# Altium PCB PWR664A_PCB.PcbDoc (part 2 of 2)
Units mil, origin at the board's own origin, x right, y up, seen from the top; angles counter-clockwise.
Board outline 3000 x 3000 mil, 4 copper layers (Top Layer, MidLayer1, MidLayer2, Bottom Layer), stack 31 mil thick; 122 components, 46 nets, 275 pads, 124 vias.
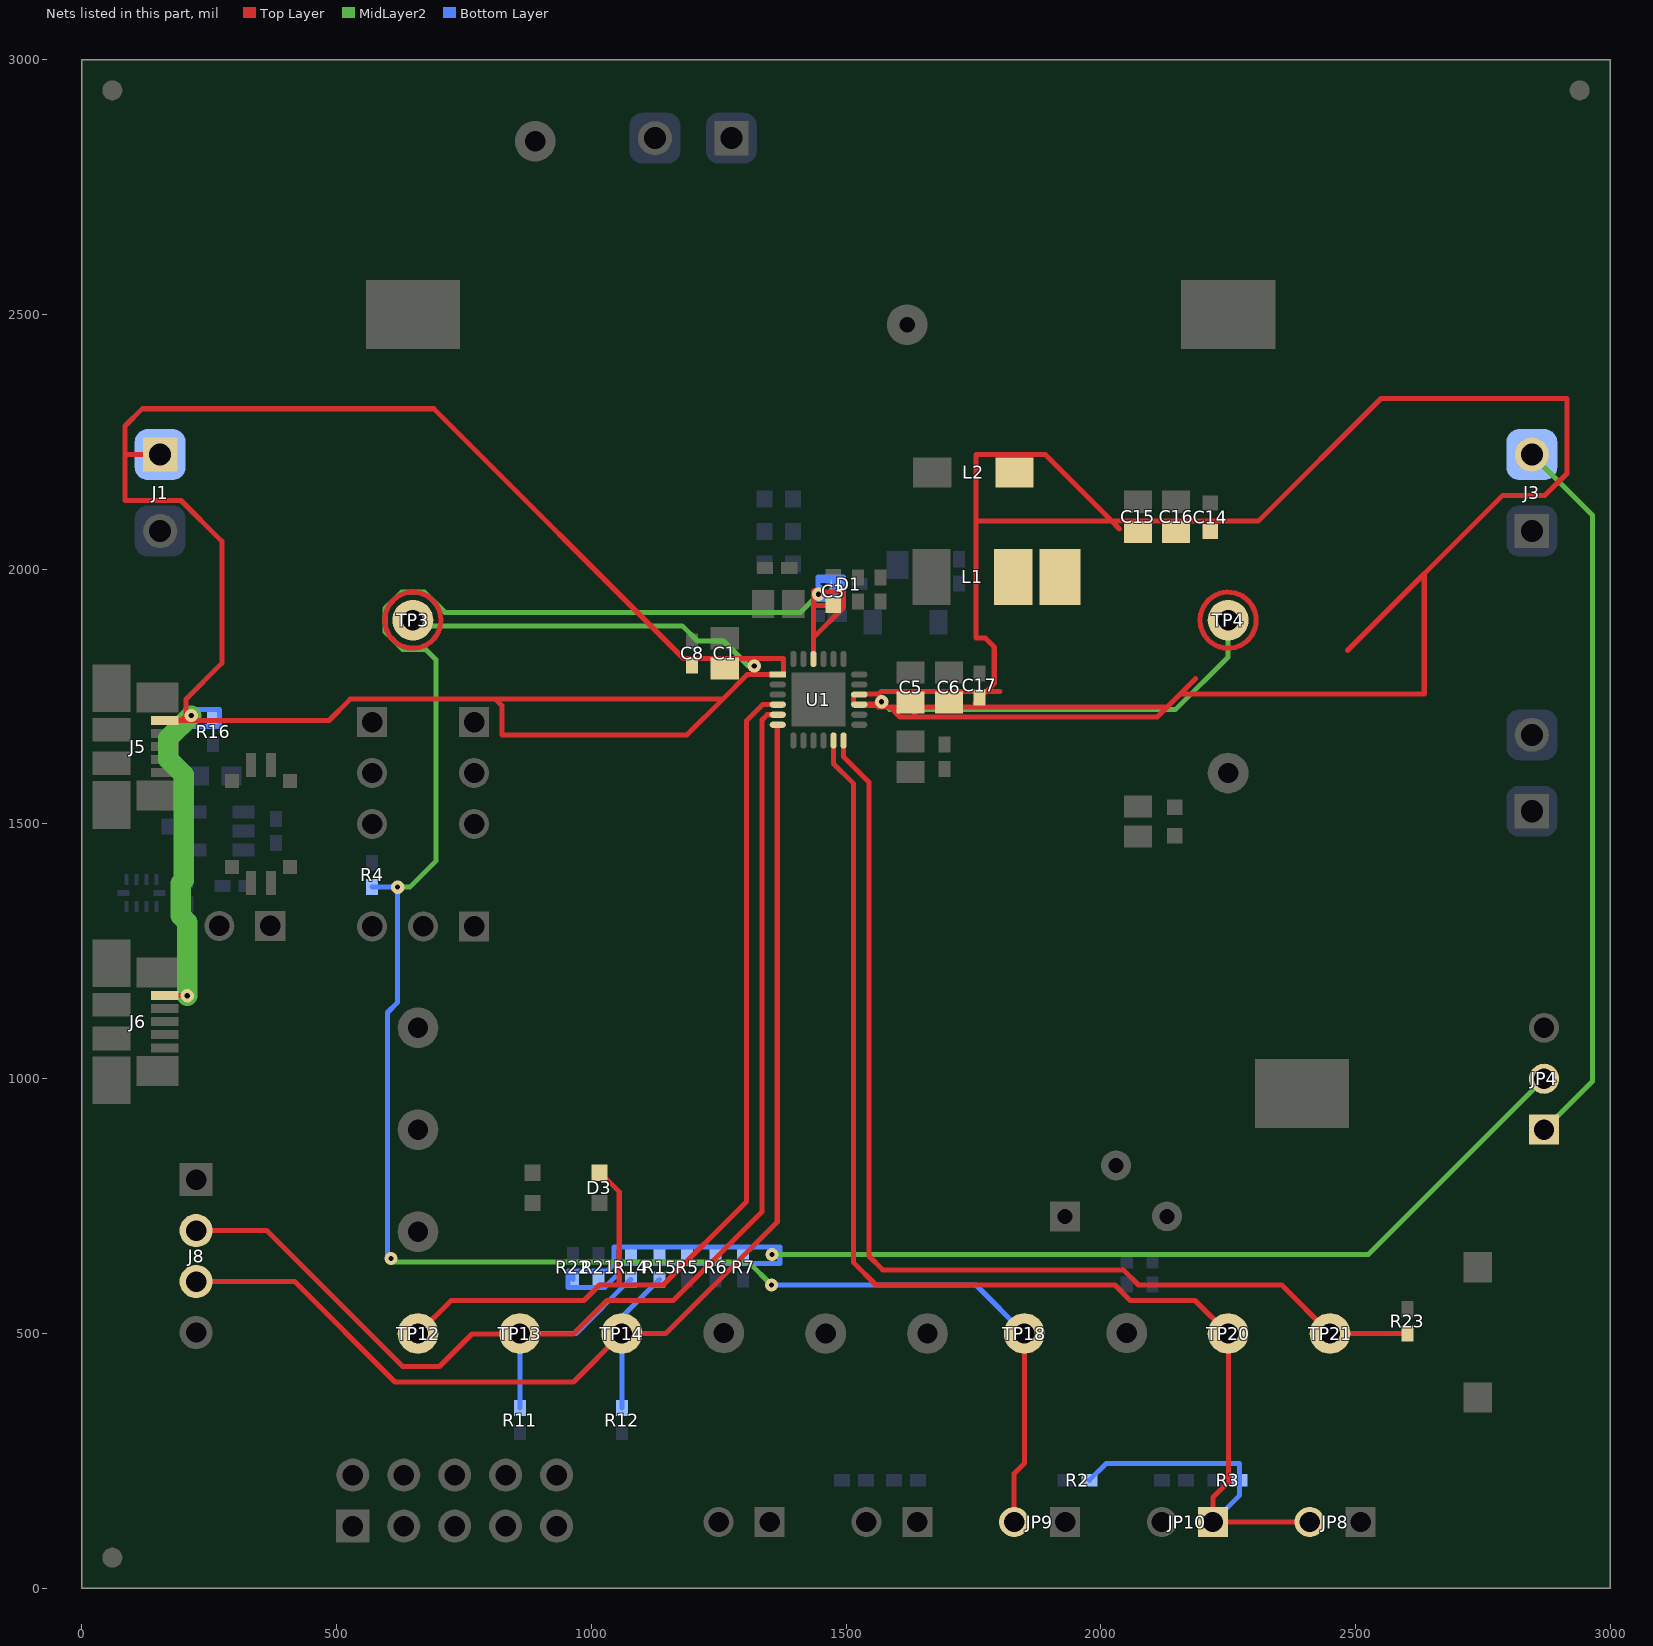
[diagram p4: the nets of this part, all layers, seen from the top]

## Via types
v1: diameter 26, hole 10, Top Layer to Bottom Layer, tented both sides, 115 vias
v2: diameter 26, hole 10, Top Layer to Bottom Layer, tented bottom, 9 vias

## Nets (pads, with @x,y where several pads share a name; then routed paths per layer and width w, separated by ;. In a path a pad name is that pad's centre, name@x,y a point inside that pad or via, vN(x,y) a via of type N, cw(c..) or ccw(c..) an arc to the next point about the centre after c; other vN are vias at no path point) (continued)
PULL-UP: JP4.2 R5.1 R6.1 R7.1 R14.1 R15.1 R21.2 R22.2 | length 2643
  MidLayer2 w10: v1(1355,655) 2525,655 JP4.2@2870,1000
  Bottom Layer w10: R22.2@964,606.38 964,612.87 954,622.87 ; 954,622.87 954,590 1026,590 1051.19,615.19 1051.19,628.34 1059.98,637.13 1370,637.13 1370,670 1045,670 1045,635.85 1032.02,622.87 954,622.87
QON: R23.2 TP21.1 U1.12 | length 2152.7
  Top Layer w10: U1.12@1495.21,1664 1495.21,1631.79 1545,1582 1545,652 1572,625 2044,625 2074,595 2355,595 TP21.1@2450,500 2601.62,500 R23.2@2602,500.38
REGN: C3.2 D1.2 JP9.2 R4.2 TP18.1 U1.22 | length 4684.4
  Top Layer w10: U1.22@1436.16,1824 1436.16,1956.87 v1@1437.47,1958.19 ; 1436.47,1866.47 1495,1925 1495,1955 1453.79,1955 1450.6,1958.19 v1@1437.47,1958.19 ; C3.2@1475,1929 1437.47,1929 v1@1437.47,1958.19 ; JP9.2@1830,130 1830,225 1850,245 TP18.1@1850,500
  MidLayer2 w10: v1(607,647) 614,640 1309,640 v1(1354,595) ; v1(620,1376) 644,1376 695,1427 695,1822.78 674.78,1843 629.22,1843 595,1877.22 595,1922.78 627.22,1955 672.78,1955 712.78,1915 1410,1915 v1(1446,1951)
  Bottom Layer w10: R4.2@570,1376.38 570.38,1376 v1(620,1376) 620,1150 600,1130 600,654 v1(607,647) ; v1@1346,595 v1(1354,595) 1755,595 TP18.1@1850,500 ; v1@1445,1952 v1@1445,1958 ; 1451,1964 v1@1445,1958 ; 1466.09,1978 1446,1978 1445,1977 ; 1478,1941 1478,1985 ; v1@1445,1958 1445,1977 ; v1@1445,1958 1438,1951 1438,1946 1443,1941 1495,1941 1495,1985 1478,1985 ; 1445,1977 1445,1985 1478,1985
SCL: J8.2 R11.1 R14.2 TP13.1 U1.5 | length 2755.9
  Top Layer w10: J8.2@224.41,702 363,702 630,435 702,435 766,499 965,499 1031,565 1161,565 1335,739 1335,1704 1345.47,1714.47 U1.5@1366,1714.47
  Bottom Layer w10: R11.1@860,353.62 TP13.1@860,500 970,500 1076.38,606.38 R14.2@1078,606.38
SDA: J8.3 R12.2 R15.2 TP14.1 U1.6 | length 2606.4
  Top Layer w10: J8.3@224.41,602 418,602 615,405 965,405 TP14.1@1060,500 1146,500 1365,719 U1.6@1365,1689.79
  Bottom Layer w10: R12.2@1060,353.62 TP14.1@1060,500 1060,532.38 R15.2@1134,606.38
STAT: D3.2 TP12.1 U1.4 | length 2006.7
  Top Layer w10: TP12.1@660,500 725,565 986,565 1016,595 1141,595 1305,759 1305,1703 1336.16,1734.16 U1.4@1366,1734.16 ; D3.2@1016,815.53 1017.47,815.53 1055,778 1055,596
SYS: C5.1 C6.1 C14.1 C15.1 C16.1 C17.1 J3.2 JP4.1 L1.2 L2.2 pad.0@1920,1985 pad.4 TP4.1 U1.15 U1.16 | length 7754.8
  Top Layer w10: U1.15@1515,1735.47 U1.16@1515,1753.84 ; U1.16@1526,1753.84 1527.16,1755 1564,1755 ; 1565,1756 1569,1760 1775.28,1760 ; C5.1@1627,1738.47 1634,1731.47 C5.1@1634,1730 ; C17.1@1753.28,1738 1775.28,1760 ; 1802,1760 1775.28,1760 ; 2037,2079 2021,2095 ; 2131,1730 C5.1@1634,1730 ; 2156,1755 2635,1755 2635,1991 ; 2186,1785 2111,1710 1634,1710 ; 2484.5,1840.5 2789,2145 2872,2145 2915,2188 2915,2334 2914,2335 2550,2335 2310,2095 2021,2095 ; v1@1559.13,1733.16 1562.73,1730.42 1563.28,1730 v1@1577,1730 ; v1@1559.13,1733.16 1526,1733.16 1526,1735.47 1557.81,1735.47 v1@1559.13,1733.16 ; v1@1559.13,1733.16 1570.44,1733.98 1572.84,1734.16 v1@1577,1730 ; v1@1577,1730 1586,1730 ; 1586,1730 1606,1710 1634,1710 ; 1586,1730 C5.1@1634,1730 ; 1634,1710 C5.1@1634,1730 ; 1755,2095 1755,1865 1773.28,1865 1791,1847.28 1791,1775.72 1775.28,1760 ; 1755,2095 1755,2225 1891,2225 2021,2095 ; 1755,2095 2021,2095 ; 2305,1900 ccw(c2250,1900) 2305,1900
  MidLayer2 w10: v1(1570,1740) 1585,1725 2147,1725 2250,1828 TP4.1@2250,1900 ; J3.2@2846,2225 2965,2106 2965,995 JP4.1@2870,900
TS: JP8.2 JP10.1 R2.1 R3.2 TP20.1 U1.11 | length 2849.8
  Top Layer w10: U1.11@1475.53,1664 1475.53,1618.47 1515,1579 1515,639 1559,595 2028,595 2058,565 2185,565 TP20.1@2250,500 ; TP20.1@2251,500 2251,209 2220,178 JP10.1@2220,130 JP8.2@2410,130
  Bottom Layer w10: R2.1@1977.62,212 2010.62,245 2272,245 2272,216.62 R3.2@2270,214.62 ; JP10.1@2220,130 2272.62,182.62 R3.2@2272.62,212
VBUS: C1.1 C8.1 J1.1 J5.1 J6.1 pad.1 R16.1 TP3.1 U1.1 | length 6071.1
  Top Layer w10: J1.1@154,2225 85,2225 ; J6.1@162.61,1163.18 206.82,1163.18 v1(207,1163) ; U1.1@1366,1793.21 1306.21,1793.21 1258,1745 ; U1.1@1377,1793 1377,1825 1181,1825 691,2315 119,2315 85,2281 85,2225 ; 85,2225 85,2135 195,2135 275,2055 275,1815.57 204.98,1745.54 204.98,1712.72 196.19,1703.93 163.36,1703.93 J5.1@162.61,1703.18 485.18,1703.18 527,1745 812,1745 ; 812,1745 1258,1745 ; 812,1745 825,1732 825,1675 1188,1675 1258,1745 ; 705,1900 ccw(c650,1900) 705,1900
  MidLayer2 w10: TP3.1@650,1900 661,1889 1178.4,1889 1208.4,1859 1259.69,1859 1308.69,1810 v1(1320,1810)
  MidLayer2 w40: v1(207,1163) 207,1307 194,1320 194,1383.81 200,1389.81 200,1597 170,1627 170,1668 v1(215,1713)
  Bottom Layer w10: v1(215,1713) v1@215,1725 ; v1@215,1725 270,1725 270,1691 205,1691 205,1725 v1@215,1725
pads on no net: FID1.1 FID2.1 FID3.1 H1.0 H2.0 H3.0 H4.0 J7.1 J7.3 J7.4 J7.5 J7.7 J7.8 SH-JP1.0 SH-JP2.0 SH-JP3.0 SH-JP4.0 SH-JP5.0 SH-JP9.0 SH-JP10.0

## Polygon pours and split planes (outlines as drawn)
AGND on Top Layer "Top Layer-No Net" (solid, remove dead copper, pour order 2): 2980,1280 2980,30 1540,30 1541,31 1541,131 1541,132 1659,250 1656,253 1656,502 1562,502 1560,500 1545,515 1545,516 1545,1280 2980,1280
PGND on Top Layer "Top Layer-No Net 1" (solid, remove dead copper, pour order 4): 1540,30 1540,129 1542,131 1661,250 1661,1710 1660,1711 207,1711 205.17,1709.17 205.17,1518.17 204.17,1518.17 129,1443 125,1439 125,1331 125,1294 185,1234 200,1234 200,1130 200,1045 185,1027 178,1020 20,1020 20,120 90,120 120,90 120,30
AGND on MidLayer2 "MidLayer2-No Net" (solid, remove dead copper, pour order 6): 20,2980 2980,2980 2980,20 20,20 20,2980
PGND on MidLayer1 "MidLayer1-No Net" (solid, remove dead copper, pour order 8): 20,2980 2980,2980 2980,20 20,20 20,2980
PGND on Bottom Layer "Bottom Layer-No Net" (solid, remove dead copper, pour order 12): 20,2980 2980,2980 2980,20 20,20 20,2980

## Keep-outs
Keep-Out Layer:
  lines w5: -5,0 ccw(c0,0) 0,-5 3000,-5 ccw(c3000,0) 3005,0 3005,3000 ccw(c3000,3000) 3000,3005 0,3005 ccw(c0,3000) -5,3000 -5,0
  text "Keep-Out Layer" at 577,-858.49 h60

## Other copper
Top Layer:
  rectangle net PGND: 1666,2436 1681,2456
  rectangle net VBUS: 647,2116 765,2204
  rectangle net VBUS: 928,1770 1068,1942
  rectangle net VBUS: 820,1734 831,1743
  rectangle net PGND: 59,2290 67,2296
  rectangle net VBUS: 85,2136 124,2284
  rectangle net VBUS: 117,2134 692,2317
  region net VBUS: 1119,1755 1184,1820 689,2315 624,2250
  rectangle net PGND: 181,980 209,1045
  rectangle net PGND: 83,1307 112,1451
  rectangle net PGND: 91,1197 115,1252
  rectangle net PGND: 81,1529 115,1585
  region net PGND: 84,1420 190,1526 138,1578 32,1472
  region net PGND: 147,1195 190,1238 89,1339 46,1296
  rectangle net PGND: 88,1179 108,1203
  rectangle net PGND: 80,987 111,1045
  rectangle net PGND: 20,850 96,1726
  region net BAT: 2731.5,1533.5 2793,1595 2734.5,1653.5 2673,1592
  region net PGND: 2755,1446 2842.5,1533.5 2803,1573 2715.5,1485.5
  region net PGND: 2922,1553 2943,1574 2928,1589 2907,1568
  region net PGND: 2890,2842 2915.5,2867.5 2874,2909 2848.5,2883.5
  region net PGND: 2935.14,2342.14 2950,2357 2937.14,2369.86 2922.28,2355
  region net SYS: 2869.5,2144.5 2914,2189 2870.5,2232.5 2826,2188
  region net PGND: 2904,2085 2966,2147 2935,2178 2873,2116
  region net PGND: 2707,1935 2848,2076 2799,2125 2658,1984
  region net SYS: 2630.5,1987.5 2787,2144 2688.5,2242.5 2532,2086
  region net SYS: 2356,2008 2616.5,2268.5 2552,2333 2291.5,2072.5
  rectangle net PMID: 847,2797 905,2871
  region net PGND: 1552,1773 1608,1829 1592,1845 1536,1789
  region net NetC4_1: 1598,1907 1632.5,1941.5 1604,1970 1569.5,1935.5
  region net NetC4_1: 1490,1835 1505.5,1850.5 1494,1862 1478.5,1846.5
  region net NetC4_1: 1533,1820 1587.86,1874.86 1555,1907.72 1500.14,1852.86
  region net PMID: 1384,2614 1444.5,2674.5 1344,2775 1283.5,2714.5
  region net PGND: 1467.64,2679.64 1543,2755 1427.64,2870.36 1352.28,2795
  region net PGND: 1226.5,2883.5 1248,2905 1208.5,2944.5 1187,2923
  region net PMID: 1174,2840.5 1206.75,2873.25 1176,2904 1143.25,2871.25
  region net PMID: 1216,2737 1241.5,2762.5 1207,2797 1181.5,2771.5
  region net PMID: 1269,2462 1383,2576 1072,2887 958,2773
  region net PMID: 881,2836 913,2868 876,2905 844,2873
  region net PGND: 816.5,2876.5 865,2925 832.5,2957.5 784,2909
  region net PMID: 874,2774 906,2806 877,2835 845,2803
  region net PGND: 849,2724 872.36,2747.36 825,2794.72 801.64,2771.36
  region net PGND: 192.5,1763.5 252,1823 215.5,1859.5 156,1800
  region net VBUS: 243,1709 312.5,1778.5 276,1815 206.5,1745.5
  region net VBUS: 490.5,1706.5 526,1742 494.5,1773.5 459,1738
  region net VBUS: 1186.5,1674.5 1304,1792 1269.5,1826.5 1152,1709
  region net PMID: 1380,2021 1426,2067 1324,2169 1278,2123
  region net PGND: 1312,1998 1343,2029 1256,2116 1225,2085
  region net PGND: 204,1999 254.5,2049.5 189,2115 138.5,2064.5
  region net VBUS: 291,2041 351,2101 257,2195 197,2135
  region net PGND: 66,2101 80,2115 65,2130 51,2116
  region net VBUS: 103,2259 136.5,2292.5 116,2313 82.5,2279.5
  region net PGND: 64,2292 107,2335 79,2363 36,2320
  region net PGND: 102,2842 145,2885 125,2905 82,2862
  rectangle net PGND: 50,2020 189,2115
  rectangle net VBUS: 1224,1748 1266,1800
  rectangle net VBUS: 1182,1718 1227,1806
  rectangle net VBUS: 1176,1793 1211,1800
  rectangle net VBUS: 1188,1793 1377,1825
  rectangle net VBUS: 825,1678 1192,1826
  rectangle net VBUS: 206,1704 487,1749
  rectangle net PGND: 185,1794 220,1825
  rectangle net PGND: 58,1771 193,1829
  rectangle net PGND: 49,1831 112,1834
  rectangle net PGND: 93,1719 112,1830
  rectangle net PGND: 36,1822 254.64,2047.08
  rectangle net PGND: 25,1822 62,2349
  rectangle net PGND: 1048,1997 1296,2080
  rectangle net PGND: 1106,1941 1332,2041
  rectangle net PGND: 976,2074 1256,2245
  rectangle net PMID: 1155,2730 1206,2875
  rectangle net PMID: 1093,2639 1344,2775
  rectangle net PMID: 876,2774 1177,2905
  rectangle net PGND: 1224,2802 1249,2933
  rectangle net PGND: 818,2923 1249,2975
  rectangle net PGND: 125,2865 825,2975
  rectangle net PGND: 1325,1872 1345,2017
  rectangle net PGND: 1201,1847 1335,2023
  rectangle net PMID: 1383,1874 1394,1887
  rectangle net PMID: 1400,1855 1416.47,1886
  rectangle net REGN: 1448,1892 1465,1930
  rectangle net REGN: 1436,1877 1452,1927
  rectangle net REGN: 1436,1922 1494,1956
  rectangle net PMID: 1374,1884 1416.47,1995
  rectangle net PMID: 1375,1986.32 1445,2127
  rectangle net PMID: 1276,2123 1446,2672
  rectangle net PGND: 1464,2259 1540,2424
  rectangle net PGND: 1236,2796.28 2873,2975
  rectangle net PGND: 1670,2242 2427,2361
  rectangle net PGND: 2934,2117 2975,2375
  rectangle net PGND: 2726,1955 2830,2055
  rectangle net PGND: 2797.28,1982 2973,2125
  rectangle net SYS: 2649,2144 2873,2200
  rectangle net SYS: 2430,2041 2684,2215
  rectangle net SYS: 2548,2189 2915,2334
  rectangle net PGND: 1515,1773 1555,1797
  rectangle net PGND: 1567,1785 1605,1824
  rectangle net NetC4_1: 1531,1852 1571,1886
  rectangle net NetC4_1: 1492,1839 1557,1865
  rectangle net NetC4_1: 1475,1816 1535,1848
  rectangle net NetC4_1: 1554,1865 1624,1953
  rectangle net PGND: 1720,1817 1762,1847
  rectangle net PGND: 1592,1788 1733,1846
  rectangle net NetC4_1: 1600,1867 1725,2095
  rectangle net BAT: 1514,1675 1553,1714
  rectangle net SYS: 1517,1729 1616,1756
  rectangle net SYS: 1755,1860 1790,2095
  rectangle net PGND: 2920,1722 2930,1731
  rectangle net PGND: 2925,1711 2977,1735
  rectangle net PGND: 2925,1554 2975,1714
  rectangle net PGND: 2802.28,1485 2971,1574
  rectangle net PGND: 2358,2355 2975,2585
  rectangle net PGND: 2358,2580 2973,2875
  rectangle net PGND: 1467,2581 2363,2805
  rectangle net PGND: 2226,2343 2363,2417
  rectangle net PGND: 2217,2352 2229,2382
  rectangle net PGND: 2164,2352 2220,2374
  rectangle net PGND: 2164,2366 2182,2382
  rectangle net PGND: 2138,2351 2176,2417
  rectangle net PGND: 1674,2331 2142,2588
  rectangle net PGND: 1645,2245 1703,2416
  rectangle net PGND: 1676,2408 1697,2450
  rectangle net PGND: 1657,2413 1681,2443
  rectangle net PGND: 1646,2413 1670,2434
  rectangle net PGND: 1465,2407 1568,2585
  rectangle net PGND: 1542,2533 1702,2603
  rectangle net PGND: 1465,2244 1594,2420
  rectangle net PGND: 1465,2057 1584,2250
  rectangle net NetC4_1: 1601,2069 1726,2225
  rectangle net NetC4_2: 1529,1971 1580,2034
  rectangle net NetC4_2: 1518,1970 1536,2004
  rectangle net AGND: 1468,1986 1494,2030
  rectangle net AGND: 1491,2014 1509,2036
  rectangle net PMID: 1411,1975 1436,1993
  rectangle net NetR13_1: 1514,1912 1534,1953
  rectangle net PGND: 1331,2011 1347,2027
  rectangle net PGND: 1341,1882 1353,2021
  rectangle net REGN: 1449,1888 1458,1897
  rectangle net REGN: 1459,1913 1488,1927
  rectangle net REGN: 1458,1905 1477,1916
  rectangle net REGN: 1459,1898 1473,1908
  rectangle net PGND: 1598,1783 1768,1842
  rectangle net NetR13_1: 1511,1902 1524,1915
  rectangle net NetR13_1: 1503,1895 1515,1906
  rectangle net NetR13_1: 1493,1886 1509,1899
  rectangle net SYS: 1609,1710 1799,1761
  rectangle net SYS: 1596,1713 1616,1728
  rectangle net BAT: 1519,1645 1578.72,1709
  rectangle net BAT: 1573,1641 1600,1691
  rectangle net BAT: 1577,1687 1590,1704
  rectangle net BAT: 1597,1637 2080,1692
  rectangle net PGND: 2657,1756 2977,1986
  rectangle net PGND: 2915,1727 2976,1763
  rectangle net PGND: 2893,1748 2920,1758
  rectangle net PGND: 2900,1742 2923,1751
  rectangle net PGND: 2906,1732 2922,1744
  rectangle net BAT: 2666,1593 2905,1710
  rectangle net BAT: 2617,1669 2883,1734
  rectangle net BAT: 2881,1711 2896,1726
  rectangle net BAT: 2306,1515 2715,1735
  rectangle net BAT: 2709,1530 2732,1554
  rectangle net BAT: 2714,1521 2725,1532
  rectangle net BAT: 1837,1515 2197,1689
  rectangle net BAT: 2192,1656 2319,1692
  rectangle net BAT: 2182,1515 2322,1546
  rectangle net BAT: 2167,1689 2314,1734
  rectangle net SYS: 2304,1755 2634,2095
  rectangle net SYS: 1788,1708 2111,2095
  rectangle net SYS: 2104,1957 2329,2096
  rectangle net SYS: 2103,1755 2196,1967
  rectangle net SYS: 2172,1755 2313,1847
  rectangle net SYS: 2104,1732 2135,1757
  rectangle net SYS: 1756,2089 1893,2223
  rectangle net SYS: 1883,2083 1956,2160
  rectangle net PGND: 2031,2118 2302,2267
  rectangle net PGND: 2284,2182 2366,2254
  rectangle net PGND: 1961,2186 2041,2258
  rectangle net PGND: 1565,1287 2975,1496
  rectangle net PGND: 1566,1492 1704,1620
  rectangle net PGND: 1696,1464 1756,1571
  rectangle net BAT: 1790,1558 1850,1655
  rectangle net PGND: 1558,1599 1571,1618
  rectangle net PGND: 26,2335 542,2871
  rectangle net PGND: 521,2336 675,2415
  rectangle net PGND: 525,2581 826,2887
  rectangle net PGND: 755,2283 1255,2445.72
  rectangle net PGND: 864,2174 1257,2292
  rectangle net PGND: 757,2439 945.72,2755
  rectangle net PGND: 921,2403 1082,2620
  rectangle net PGND: 1071,2416 1176,2528
  rectangle net PGND: 936,2597 1026,2675
  rectangle net VBUS: 273,1745 597,2149
  rectangle net VBUS: 702,1744 955,1978
  rectangle net VBUS: 557,1956 815,2146
  rectangle net VBUS: 568,1747 708,1845
  rectangle net PGND: 25,1724 97,1827
  region net BAT: 2199,1621 2232,1654 2211,1675 2178,1642
  region net BAT: 2315.5,1607.5 2345,1637 2297.5,1684.5 2268,1655
  region net BAT: 2285,1520 2329,1564 2307,1586 2263,1542
  region net BAT: 2217,1521 2236.5,1540.5 2197,1580 2177.5,1560.5
  region net BAT: 2139,1657 2191.5,1709.5 2168,1733 2115.5,1680.5
  region net SYS: 2113,1715 2154,1756 2127,1783 2086,1742
  region net SYS: 2194,1916 2235,1957 2210,1982 2169,1941
  region net SYS: 2313.5,1909.5 2337,1933 2290.5,1979.5 2267,1956
  region net SYS: 2279,1819 2322,1862 2304,1880 2261,1837
  region net SYS: 2219,1819 2239,1839 2196,1882 2176,1862
  region net PGND: 2304.36,2117.64 2539.72,2353 2462.36,2430.36 2227,2195
  region net PGND: 2032,2114 2112,2194 1984,2322 1904,2242
  region net SYS: 1975,2054 2018,2097 1891,2224 1848,2181
  region net PGND: 1565.5,2497.5 1606.5,2538.5 1570,2575 1529,2534
  region net PGND: 1681.5,2492.5 1712,2523 1664.5,2570.5 1634,2540
  region net PGND: 1576.5,2405.5 1597,2426 1560.5,2462.5 1540,2442
  region net PGND: 1174,2366 1254.36,2446.36 946.72,2754 866.36,2673.64
  region net PGND: 1191,1847 1244,1900 1096,2048 1043,1995
  region net PGND: 1188,1851 1240.5,1903.5 1096,2048 1043.5,1995.5
  region net PGND: 1196,1843 1208.5,1855.5 1203,1861 1190.5,1848.5
  region net PGND: 1056.5,1982.5 1145,2071 844.5,2371.5 756,2283
  region net PGND: 762.5,2275.5 810,2323 748.5,2384.5 701,2337
  region net PGND: 721,2327 782.5,2388.5 754,2417 692.5,2355.5
  region net PGND: 671,2351 692,2372 677,2387 656,2366
  region net VBUS: 869,1888 947.5,1966.5 819,2095 740.5,2016.5
  region net VBUS: 597.5,1921.5 632,1956 606.5,1981.5 572,1947
  region net VBUS: 712,1913 743,1944 700,1987 669,1956
  region net VBUS: 672,1812 720,1860 702,1878 654,1830
  region net VBUS: 620,1819 640,1839 598,1881 578,1861
  region net PGND: 1791,1449 1833,1491 1704,1620 1662,1578
  region net BAT: 1837,1517 1876.5,1556.5 1758,1675 1718.5,1635.5
  region net SYS: 1790,1852 1801,1863 1791,1873 1780,1862
  rectangle net PGND: 727,2391 762,2416
  rectangle net PGND: 667,2334 725,2372
  text "Top Layer" at 577,-858.49 h60
MidLayer1:
  text "MidLayer1" at 577,-858.49 h60
MidLayer2:
  rectangle net AGND: 1462,2305 1567,2635
  rectangle net AGND: 1677,2326 1783,2638
  rectangle net AGND: 1383,1677 1520,1809
  text "MidLayer2" at 577,-858.49 h60
Bottom Layer:
  rectangle net REGN: 1443,1943 1476,1983
  rectangle net PMID: 1374,1913 1418,1984
  rectangle net PMID: 1374,1972 1427,2156
  rectangle net PULL-UP: 1319,641 1368,670
  rectangle net PULL-UP: 1047,631.15 1054,644
  rectangle net PULL-UP: 1041,611 1050,643
  rectangle net PULL-UP: 1033,605 1043,627
  rectangle net PULL-UP: 1022,596 1036,622.87
  rectangle net PULL-UP: 959,591 1027,623
  rectangle net PULL-UP: 1044,637.13 1323.13,670
  region net NetC23_1: 343.5,1511.5 354,1522 341.5,1534.5 331,1524
  region net NetC23_1: 362,1506 371,1515 340,1546 331,1537
  region net NetC23_1: 317.5,1535.5 333,1551 296.5,1587.5 281,1572
  region net PGND: 269,1536 277.5,1544.5 257,1565 248.5,1556.5
  rectangle net 3.3V: 174,1441 184,1452
  rectangle net 3.3V: 181,1370 190,1380
  rectangle net 3.3V: 181,1394 200,1419
  rectangle net 3.3V: 172,1378 204,1404
  rectangle net 3.3V: 163,1366 182.85,1396
  rectangle net NetC22_1: 232,1418 244,1430
  rectangle net NetC22_1: 209,1427 245,1438
  rectangle net NetC22_1: 243,1381 255,1391
  rectangle net PGND: 274,1411 285,1419
  rectangle net PGND: 267,1411 277,1427
  rectangle net PGND: 306,1403 315,1413
  rectangle net PGND: 312,1387 340,1415
  rectangle net NetR10_1: 362,1453 374,1468
  rectangle net NetR10_1: 297,1435 394,1459
  rectangle net PGND: 265,1463 277,1540
  rectangle net NetC23_1: 314,1527 338,1550
  rectangle net NetC23_1: 297,1529 318,1578
  rectangle net NetC23_1: 363,1502 390,1525
  rectangle net 3.3V: 153,1450 188,1485
  rectangle net 3.3V: 192,1498 216,1522
  rectangle net 3.3V: 150,1480 245,1513
  rectangle net PGND: 197.28,1587 206,1597
  rectangle net PGND: 181,1569 194,1584
  rectangle net PGND: 163,1547 186,1566
  rectangle net PGND: 149,1531 177.13,1548.72
  rectangle net PGND: 189,1562 209,1593
  rectangle net PGND: 201,1567 221,1604
  rectangle net PGND: 173,1554 223,1575
  rectangle net PGND: 211,1554 255,1615
  rectangle net NetC23_1: 274,1573 315,1636
  rectangle net NetC23_1: 245,1633 314,1673
  rectangle net VBUS: 204,1691 270,1727
  rectangle net REGN: 1458,1945 1495,1982
  rectangle net NetC4_2: 1514,1961 1547,1996
  rectangle net NetC4_2: 1529,1990 1556,2036
  rectangle net NetC21_1: 1660,2005 1714,2035
  rectangle net NetC21_1: 1677,1982 1690,2008
  rectangle net NetC21_1: 1686,1997 1698,2008
  rectangle net NetC4_1: 1573,1914 1623,2033
  rectangle net NetC4_1: 1565,1877 1588,1980
  rectangle net NetC4_1: 1585,1904 1616,1917
  rectangle net NetC4_1: 1582,1895 1606,1906
  rectangle net NetC4_1: 1586,1886 1598,1899
  rectangle net NetC4_1: 1514,1892 1567,1942
  rectangle net NetC4_1: 1526,1877 1542,1895
  rectangle net NetC4_1: 1518,1883 1531,1895
  rectangle net NetC4_1: 1499,1896 1521,1923
  rectangle net NetC4_1: 1510,1918 1520,1928
  rectangle net PMID: 1405,1898 1448,1921
  rectangle net PMID: 1420,1917 1429,1928
  text "Bottom Layer" at 577,-858.49 h60

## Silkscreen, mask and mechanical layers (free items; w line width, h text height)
Top Overlay:
  text "PMID" at 702,2795 h40
  text "PMID" at 1058,2636 h40
  text "GND" at 1233,2635 h40
  text "SW" at 1720,2526 h40
  text "TP1" at 1718,2452 h40
  text "PGND" at 782,2441 h40
  text "PGND" at 2381,2439 h40
  text "SYS" at 2586,2208 h40
  text "VBUS" at 321,2201 h40
  text "GND" at 319,2054 h40
  text "GND" at 2580,2052 h40
  text "VBUS" at 724,1880 h40
  text "SYS" at 2329,1852 h40
  text "USB IN" at 23,1833 h30
  text "LOW" at 646,1798 h30 r270
  text "D-" at 849,1769 h30 r270
  text "D+/PSEL" at 646,1683 h30 r270
  text "D-/PG" at 847,1670 h30 r270
  text "BAT" at 2582,1653 h40
  text "BAT" at 2332,1548 h40
  text "GND" at 2582,1500 h40
  text "PG" at 847,1497 h30 r270
  text "HIGH" at 647,1487 h30 r270
  text "USB OUT" at 20,1300 h30
  text "DSEL" at 531,1199 h30
  text "PG" at 750,1199 h30
  text "D+" at 253,1198 h30
  text "D-" at 344,1198 h30
  text "PWR664_ReV A" at 1939,1169 h40
  text "BAT" at 2969,1070 h30 r90
  text "DSEL" at 467,1059 h40
  text "AGND" at 2527,928 h40
  text "PULL-UP" at 2795,917 h30 r90
  text "SYS" at 2970,858 h30 r90
  text "D-/PG" at 410,853 h40
  text "GND" at 281,844 h30 r270
  text "SCL" at 282,741 h30 r270
  text "PG" at 858,688 h30
  text "STAT" at 968,688 h30
  text "D+/PSEL" at 371,654 h40
  text "SDA" at 282,642 h30 r270
  text "/CE" at 282,543 h30 r270
  text "REGN" at 1780,390 h40
  text "\CE" at 1610,388 h40
  text "ILIM" at 2012,388 h40
  text "QON" at 2399,388 h40
  text "SCL" at 814,387 h40
  text "INT" at 1230,387 h40
  text "TS" at 2219,387 h40
  text "STAT" at 595,386 h40
  text "OTG" at 1410,386 h40
  text "SDA" at 1013,385 h40
  text "OTG" at 1209,29 h30
  text "GND" at 1321,28 h30
  text "GND" at 1605,28 h30
  text "REGN" at 1782,27 h30
  text "TS" at 2200,27 h30
  text "TS" at 2390,27 h30
  text "\CE" at 1501,26 h30
  text "GND" at 2477,26 h30
  text "Top Overlay" at 577,-858.49 h60
Bottom Overlay:
  text "Bottom Overlay" at 577,-858.49 h60
Top Paste:
  text "Top Paste" at 577,-858.49 h60
Bottom Paste:
  text "Bottom Paste" at 577,-858.49 h60
Top Solder:
  text "Top Solder" at 577,-858.49 h60
Bottom Solder:
  text "Bottom Solder" at 577,-858.49 h60
Drill Guide:
  text "Drill Guide" at 577,-858.49 h60
M1 Board Outline:
  the board outline again, w5
  text "M1 Board Outline" at 577,-858.49 h60
M2 Board Dimensions:
  rectangle: 124.5,-410.5 499.5,-285.5
  rectangle: -0.5,-285.5 124.5,-160.5
  lines w7: -0.5,-285.5 999.5,-285.5 ; 124.5,-410.5 124.5,-160.5 ; 249.5,-410.5 249.5,-160.5 ; 499.5,-410.5 499.5,-160.5 ; 749.5,-410.5 749.5,-160.5 ; -0.5,-410.5 -0.5,-160.5 999.5,-160.5 999.5,-410.5 -0.5,-410.5
  lines w10: -0.5,-475.5 -0.5,-455.5 ; 59.5,-485.5 -0.5,-465.5 ; 59.5,-445.5 -0.5,-465.5 ; 223.58,-465.5 -0.5,-465.5 ; 775.42,-465.5 999.5,-465.5 ; 939.5,-485.5 999.5,-465.5 ; 939.5,-445.5 999.5,-465.5 ; 999.5,-475.5 999.5,-455.5
  text "1000 (mil)" at 233.58,-501.49 h60
  text "M2 Board Dimensions" at 577,-858.49 h60
M3 3D STEP Top:
  text "M3 3D STEP Top" at 577,-858.49 h60
M4 3D STEP Bottom:
  text "M4 3D STEP Bottom" at 577,-858.49 h60
M5 Assembly Top:
  lines w7: 3546,614.5 4671,614.5 ; 3546,737 4668.5,737 ; 3861,374.5 3861,857 ; 4246,374.5 3546,374.5 ; 4246,494.5 3546,494.5 ; 4246,857 3546,857 ; 3546,374.5 4671,374.5 4671,494.5 ; 3546,374.5 3546,494.5 ; 3546,494.5 4671,494.5 ; 3546,494.5 3546,857 ; 3546,857 4671,857 4671,494.5
  lines w10: -292,-930.17 6308,-930.17 ; -292,-726.83 6310,-726.83 ; -292,-523.5 -292,-1133.5 3713,-1133.5 6310,-1133.5 6310,-523.5 -291.5,-523.5 -291.5,-1133.5 1284,-1133.5 ; 2173,-1133.5 2173,-523.5 ; 3440,-726.83 3440,-523.5 ; 4280,-726.83 4280,-523.5 ; 4902,-1140 4902,-937.17
  text "TABLE 1" at 3933.5,892 h40
  text "Variant" at 3571,782 h40
  text "Label text" at 4006,782 h40
  text "001" at 3638.5,662 h40
  text "BQ25890EVM-664" at 3916,659.5 h40
  text "002" at 3638.5,536 h40
  text "BQ25892EVM-664" at 3913,535.5 h40
  text "BQ25895EVM-664" at 3916,420.5 h40
  text "003" at 3640.5,417 h40
  text "COMPONENTS MARKED 'DNP' SHOULD NOT BE POPULATED." at 1153.5,-318.5 h60
  text "ASSEMBLY VARIANT:" at 1153,-434 h60
  text "001" at 2189,-434 h60
  text "PCB VIEWED FROM TOP SIDE" at -228.5,-655.67 h60
  text "BOARD #:" at 2248,-655.67 h60
  text "PWR664" at 2793.5,-655.67 h60
  text "REV:" at 3638,-655.67 h60
  text "A" at 3929.5,-655.67 h60
  text "SVN REV:" at 4476,-655.67 h60
  text "IGNORE ->" at -228.5,-858.49 h60
  text "PLOT NAME =" at -228.5,-1064.34 h60
  text "GENERATED    :" at 2250,-1064.34 h60
  text "02/23/2015" at 3119.5,-1064.34 h60
  text "TEXAS INSTRUMENTS" at 5113,-1064.34 h60
M6 Assembly Bottom:
  lines w10: -292.5,-727.33 6309.5,-727.33 ; -290.5,-930.67 6309.5,-930.67 ; 1115.5,-1140.5 1115.5,-937.67 ; 1737.5,-727.33 1737.5,-524 ; 2577.5,-727.33 2577.5,-524 ; 3844.5,-1134 3844.5,-524 ; 4733.5,-1134 6309,-1134 6309,-524 -292.5,-524 -292.5,-1134 2304.5,-1134 6309.5,-1134 6309.5,-524
  text "COMPONENTS MARKED 'DNP' SHOULD NOT BE POPULATED." at 6102,-318 h60
  text "001" at 5058,-434 h60
  text "ASSEMBLY VARIANT:" at 6097,-434 h60
  text "SVN REV:" at 1541.5,-656.17 h60
  text "A" at 2088,-656.17 h60
  text "REV:" at 2379.5,-656.17 h60
  text "PWR664" at 3224,-656.17 h60
  text "BOARD #:" at 3769.5,-656.17 h60
  text "PCB VIEWED FROM BOTTOM SIDE" at 6246,-656.17 h60
  text "IGNORE ->" at 2547.85,-858.49 h60
  text "TEXAS INSTRUMENTS" at 904.5,-1064.84 h60
  text "02/23/2015" at 2898,-1064.84 h60
  text "GENERATED    :" at 3767.5,-1064.84 h60
  text "PLOT NAME =" at 6246,-1064.84 h60
M9 Title Sheet:
  drawing of 57 lines, arcs and shapes, not listed
  text "1" at 739.84,8036.5 h70
  text "2" at 3235.5,8036.5 h70
  text "3" at 5724.84,8036.5 h70
  text "4" at 8231.51,8036.5 h70
  text "5" at 10730.5,8036.5 h70
  text "6" at 13235.5,8036.5 h70
  text "A" at -416.5,6893.5 h70
  text "A" at 14383.5,6893.5 h70
  text "B" at -416.5,4513.5 h70
  text "B" at 14383.5,4513.5 h70
  text "C" at -416.5,2138.5 h70
  text "C" at 14383.5,2138.5 h70
  text "PROJECT TITLE:" at 11343.5,277.5 h45
  text "bq2589x_EVM" at 11393.5,144.17 h70
  text "DESIGNED FOR:" at 11343.5,-23.5 h45
  text "Public Release" at 11393.5,-163.5 h70
  text "D" at -416.5,-231.5 h70
  text "D" at 14383.5,-231.5 h70
  text "FILE NAME:" at 11343.5,-323.5 h45
  text "PWR664ReV A.PCBDOC" at 11393.5,-443.5 h70
  text "Texas Instruments (TI) and/or its licensors do not warrant the accuracy or completeness of this specification" at 6374,-605.34 h45
  text "ENGINEER:" at 11343.5,-613.5 h45
  text "LAYOUT BY:" at 12848.5,-613.5 h45
  text "or any information contained therein. TI and/or its licensors do not warrant that this design will meet" at 6329.01,-718 h45
  text "Samuel Wong" at 11393.5,-768.49 h70
  text "Alex Ji" at 12899,-768.49 h70
  text "the specifications, will be suitable for your application or fit for any particular purpose, or will operate in" at 6329.01,-830.67 h45
  text "M9 Title Sheet" at 577,-858.49 h60
  text "ALTIUM DESIGNER VERSION:" at 12848.5,-923.5 h45
  text "an implementation. TI and/or its licensors do not warrant that the design is production worthy. You should" at 6329.01,-943.33 h45
  text "completely validate and test your design implementation to confirm the system functionality for your application." at 6374,-1056 h45
  text "1" at 739.84,-1263.5 h70
  text "2" at 3235.5,-1263.5 h70
  text "3" at 5724.84,-1263.5 h70
  text "4" at 8231.51,-1263.5 h70
  text "5" at 10730.5,-1263.5 h70
  text "6" at 13235.5,-1263.5 h70
M10 Fab Notes:
  drawing of 212 lines, arcs and shapes, not listed
  text "DESIGN INFORMATION" at 12381.02,6810 h60
  text "(REFER ALSO ARRAY/PANEL PROFILING INFORMATION)" at 12019.46,6648.29 h60
  text "BOARD SIZE" at 11333.46,6644 h60
  text "3000MIL" at 11795.78,6516.18 h60
  text "X" at 12301.46,6516.18 h60
  text "3000MIL" at 12532.78,6516.18 h60
  text "Number of Layers :" at 11736.46,6319 h60
  text "4" at 12831.27,6309 h60
  text "MIN. TRACK WIDTH:" at 11736.46,6180 h60
  text "10" at 12832.7,6180 h60
  text "MIL" at 12987.46,6180 h60
  text "MIN. CLEARANCE:" at 11736.46,6048 h60
  text "6" at 12832.7,6048 h60
  text "MIL" at 12987.46,6048 h60
  text "MIN. VIA PAD SIZE:" at 11736.46,5916 h60
  text "10" at 12802.71,5916 h60
  text "MIL" at 12987.46,5916 h60
  text "0.05mm (2MIL)" at 12431.46,5774.29 h60
  text "MINIMUM ANNULAR RING" at 11407.23,5770 h60
  text "EXTERNAL" at 13139.46,5770 h60
  text "PER" at 11607.23,5652 h60
  text "IPC-D-275 CLASS 2 LEVEL C" at 11827.23,5652 h60
  text "MIL, HOLES" at 13315.46,5539.71 h60
  text "+/-" at 12923,5539 h60
  text "+/-" at 13777,5539 h60
  text "REGISTRATION TOLERANCES:" at 11407.23,5534 h60
  text "METAL" at 12607,5534 h60
  text "5" at 13183.2,5534 h60
  text "3" at 14016.2,5534 h60
  text "MIL" at 14132.46,5534 h60
  text "MATERIAL:" at 11332.46,5324.54 h60
  text "FR-4 High Tg" at 12318.9,5184.21 h60
  text "FR-408" at 11753.46,5175.64 h60
  text "X" at 12165.46,5175.64 h60
  text "OTHER" at 13241.46,5175.64 h60
  text "31 MIL" at 13662.56,5024.92 h60
  text "62 MIL (1.6mm) +/-10%" at 12073.56,5012.92 h60
  text "THICKNESS:" at 11407.23,5008.64 h60
  text "X" at 13231.4,5008.64 h60
  text "OTHER" at 13358.46,5008.64 h60
  text "TOLERANCE:" at 11407.23,4850.64 h60
  text "X" at 12246.53,4850.64 h60
  text "ANSI IPC-6012 TYPE 3 CLASS 2" at 12433.48,4850.64 h60
  text "OTHER +/-" at 12433.46,4694.64 h60
  text "BOW & TWIST:" at 11407.23,4537.64 h60
  text "X" at 12246.53,4537.64 h60
  text "ANSI IPC-6012 TYPE 3 CLASS 2" at 12433.48,4537.64 h60
  text "OTHER +/-" at 12433.46,4379.13 h60
  text "COPPER THICKNESS (FINISHED):" at 11332.46,4243.64 h60
  text "1.4MIL (1oz)" at 12212.46,4090.92 h60
  text "2MIL (1.4oz)" at 12979.46,4090.92 h60
  text "2.8MIL (2oz)" at 13706.46,4090.92 h60
  text "OUTER:" at 11689.46,4086.64 h60
  text "X" at 13578,4086 h60
  text "1.4MIL (1oz)" at 12212.46,3933.92 h60
  text "2.8MIL (2oz)" at 12979.46,3933.92 h60
  text "N/A" at 13706,3934.29 h60
  text "X" at 12853,3932 h60
  text "INNER SIGNAL:" at 11400.38,3929.64 h60
  text "DRILLING:" at 11332.46,3790.64 h60
  text "REFERENCE:" at 11407.23,3673.64 h60
  text "X" at 12055.46,3673.64 h60
  text "AS SHOWN" at 12242.46,3673.64 h60
  text "X" at 12956.46,3673.64 h60
  text "NC_DRILL FILES" at 13093.46,3673.64 h60
  text "PTH MIN COPPER THICKNESS:" at 11407.23,3515.64 h60
  text "X" at 12757.46,3515.64 h60
  text "1MIL" at 12894.46,3515.64 h60
  text "OTHER" at 13391.46,3515.64 h60
  text "BOARD FINISH:" at 11332.46,3356.64 h60
  text "SILKSCREEN:" at 11487.68,3238.64 h60
  text "X" at 12436.46,3238.64 h60
  text "TOP" at 12562.46,3238.64 h60
  text "X" at 12946.46,3238.64 h60
  text "BOTTOM" at 13073.46,3238.64 h60
  text "SILKSCREEN COLOR:" at 11487.68,3071.64 h60
  text "X" at 12435.42,3071.64 h60
  text "WHITE" at 12562.46,3071.64 h60
  text "OTHER" at 13073.46,3071.64 h60
  text "SOLDER RESIST COLOR:" at 11487.68,2901.64 h60
  text "X" at 12055.42,2742.44 h60
  text "GREEN" at 12182.46,2742.44 h60
  text "BLUE" at 12773.46,2742.44 h60
  text "OTHER" at 13311.46,2742.44 h60
  text "IMMERSION GOLD (ENIG)" at 12393.46,2553.92 h60
  text "ENEPIG" at 13731,2550.64 h60
  text "SURFACE FINISH:" at 11332.46,2549.64 h60
  text "X" at 12206.51,2549.64 h60
  text "IMM. TIN/SILVER OR EQUIV" at 11662,2392.64 h60
  text "OTHER" at 13093.46,2392.64 h60
  text "ARRAY/PANEL:" at 11332.46,2213.64 h60
  text "CUT AND TRIM PER MECH LAYER 1" at 12393.46,2209.35 h60
  text "N.C. ROUTE" at 12393.46,2057.64 h60
  text "X" at 13072.46,2057.64 h60
  text "V. SCORE" at 13259.46,2057.64 h60
  text "CERTIFICATION:" at 11332.46,1920.64 h60
  text "MATERIALS AND WORKMANSHIP FOR ALL PCBS" at 12057.46,1920.64 h60
  text "TO MEET OR EXCEED THE REQUIREMENTS OF:" at 12057.46,1822.64 h60
  text "X" at 11683.96,1686.13 h60
  text "ANSI IPC-A-600F CLASS ->" at 11822.96,1686.13 h60
  text "X" at 13462.02,1686.13 h60
  text "2" at 13580.96,1686.14 h60
  text "1" at 13265.96,1684.64 h60
  text "3" at 13934.96,1684.64 h60
  text "X" at 11686.02,1526.64 h60
  text "UL 94V-0" at 11822.96,1526.64 h60
  text "X" at 12498.02,1526.64 h60
  text "RoHS" at 12634.96,1526.64 h60
  text "OTHER" at 13279.36,1526.64 h60
  text "PER ORDER" at 13676.42,1526.64 h60
  text "ADDITIONAL REQUIREMENTS:" at 11332.46,1385.64 h60
  text "MICROSECTION:" at 11407.23,1270.64 h60
  text "YES" at 12312.96,1270.64 h60
  text "REQUIRED" at 13174.46,1114.49 h60
  text "BARE BOARD ELEC. TEST:" at 11407.23,1111.64 h60
  text "NONE" at 12712.96,1111.64 h60
  text "X" at 13047.46,1111.64 h60
  text "PER ORDER" at 13766.46,1111.64 h60
  text "MANUFACTURER'S UL:" at 11407.23,954.64 h60
  text "RAIL" at 12572.96,950.35 h60
  text "METAL" at 13064.77,950.35 h60
  text "X" at 13440,950 h60
  text "SILK" at 13576.46,950.35 h60
  text "M10 Fab Notes" at 577,-858.49 h60
M11 Gerber Information:
  lines w10: -292,-930.17 6308,-930.17 ; -292,-726.83 6310,-726.83 ; -292,-523.5 -292,-1133.5 3713,-1133.5 6310,-1133.5 6310,-523.5 -291.5,-523.5 -291.5,-1133.5 1284,-1133.5 ; 2173,-1133.5 2173,-523.5 ; 3440,-726.83 3440,-523.5 ; 4280,-726.83 4280,-523.5 ; 4902,-1140 4902,-937.17
  text "ALL ARTWORK VIEWED FROM TOP SIDE" at -228.5,-655.67 h60
  text "BOARD #:" at 2248,-655.67 h60
  text "PWR664" at 2793.5,-655.67 h60
  text "REV:" at 3638,-655.67 h60
  text "A" at 3929.5,-655.67 h60
  text "SVN REV:" at 4476,-655.67 h60
  text "LAYER NAME =" at -228.5,-858.49 h60
  text "PLOT NAME =" at -228.5,-1064.34 h60
  text "GENERATED    :" at 2250,-1064.34 h60
  text "02/23/2015" at 3119.5,-1064.34 h60
  text "TEXAS INSTRUMENTS" at 5113,-1064.34 h60
M12 Stackup:
  lines w5: 11365,7525.5 14210,7525.5 ; 11365,7608.4 14210,7608.4 ; 11305,6992 ccw(c11332,6992) 11332,6965 14243,6965 ccw(c14243,6992) 14270,6992 14270,7682 ccw(c14243,7682) 14243,7709 11332,7709 ccw(c11332,7682) 11305,7682 11305,6992
  text "The Stackup Legend below this is static." at 11605.5,7874.5 h60
  text "If you change the stackup, update the Legend." at 11615.5,7784.5 h60
  text "Layer Stack Up Detail for: PWR664RevA_PCB.PcbDoc" at 11365,7630.8 h38
  text "Layer" at 11365,7577.4 h19
  text "Gerber" at 12350.19,7577.4 h19
  text "Copper" at 13069.92,7577.4 h19
  text "Dielectric" at 13820.68,7577.4 h19
  text "Name" at 11365,7539.4 h19
  text "Document" at 12350.19,7539.4 h19
  text "Thickness" at 13069.92,7539.4 h19
  text "Material" at 13820.68,7539.4 h19
  text "Top Solder Mask" at 11365,7484.25 h27
  text "(.GTS)" at 12350.19,7484.25 h27
  text "Solder Resist" at 13820.68,7484.25 h27
  text "Top Layer" at 11365,7406.75 h27
  text "(.GTL)" at 12350.19,7406.75 h27
  text "2.8mil" at 13069.92,7406.75 h27
  text "FR-4" at 13820.68,7368 h27
  text "MidLayer1" at 11365,7329.25 h27
  text "(.G1)" at 12350.19,7329.25 h27
  text "2.8mil" at 13069.92,7329.25 h27
  text "FR-4" at 13820.68,7290.5 h27
  text "MidLayer2" at 11365,7251.75 h27
  text "(.G2)" at 12350.19,7251.75 h27
  text "2.8mil" at 13069.92,7251.75 h27
  text "FR-4" at 13820.68,7213 h27
  text "Bottom Layer" at 11365,7174.25 h27
  text "(.GBL)" at 12350.19,7174.25 h27
  text "2.8mil" at 13069.92,7174.25 h27
  text "Bottom Solder Mask" at 11365,7096.75 h27
  text "(.GBS)" at 12350.19,7096.75 h27
  text "Solder Resist" at 13820.68,7096.75 h27
  text "M12 Stackup" at 577,-858.49 h60
M13 Component Bodies Top:
  text "M13 Component Bodies Top" at 577,-858.49 h60
M14 Component Bodies Bottom:
  text "M14 Component Bodies Bottom" at 577,-858.49 h60
M15 Courtyards Top:
  text "M15 Courtyards Top" at 577,-858.49 h60
M16 Courtyards Bottom:
  text "M16 Courtyards Bottom" at 577,-858.49 h60
Drill Drawing:
  text "Legend is not interpreted until output" at 3517.5,1217.5 h60
  text "Drill Table" at 3554.5,1044.5 h60
  text "Drill Drawing" at 577,-858.49 h60

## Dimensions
0,0 to 3000,0 on M2 Board Dimensions
0,0 to 0,3000 on M2 Board Dimensions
